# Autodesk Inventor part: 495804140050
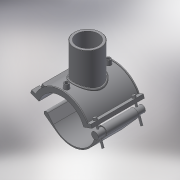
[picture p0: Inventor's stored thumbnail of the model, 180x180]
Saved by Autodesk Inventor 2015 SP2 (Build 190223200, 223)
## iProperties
Created: 2017-07
Part Number: 495804140050
Material: Generic
Description: PLASSON BRANCH SADDLE 140-50
Document SubType Name: Modeling
Designer: KIM
Density: 1 g/cm^3
Appearance: Default
Author: KIM
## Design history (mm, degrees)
derived "495804.ipt"
feature "Solid1::495804.ipt"
feature "Solid2::495804.ipt"
tag "TaggingFeature1"
body "Solid1"
body "Solid2"
other parameters: "d3" = 35, "d4" = 118, "d5" = 0, "d6" = 0.1, "d8" = 0, "d19" = 6, "d20" = 6, "d21" = 70.8, "d23" = 0, "d24" = 35.4, "d26" = 0, "d27" = 3, "d28" = 3, "d29" = 3, "d30" = 46.66667, "d31" = 6, "d32" = 0, "d33" = 0, "d34" = 0.6, "d40" = 84.24, "d41" = 55, "d43" = 0, "d45" = 0, "d47" = 174, "d50" = 0, "d70" = 15, "d72" = 0, "d73" = 6, "d75" = 5, "d76" = 0, "d77" = 7, "d79" = 15, "d80" = 47.2, "d82" = 5 deg, "d84" = 4, "d85" = 14, "d86" = 0, "d87" = 3, "d88" = 0, "d89" = 1, "d90" = 1, "d91" = 94.4, "d92" = 0, "d93" = 0.5, "d94" = 73.68421, "d96" = 165.24, "d97" = 2.36, "d98" = 0, "d102" = 1.5, "d105" = 0, "d109" = -31, "d117" = 0.5, "d120" = 140 deg, "d121" = 24.228, "d122" = 20 deg, "d123" = 324, "d124" = 97.2, "d126" = 0, "d143" = 147, "d150" = 25.2, "d159" = 4.4, "d161" = 3.5, "d162" = 70.8, "d163" = 0, "d167" = 28, "d168" = 73.63636, "d173" = 1, "d176" = 20 deg, "d177" = 9.8, "d178" = 22, "d180" = 0, "d185" = 38.35, "d186" = 38.35, "d187" = 81, "d188" = 6.6, "d189" = 9.8, "d190" = 0, "d191" = 121.5, "d200" = 11, "d202" = 0, "d216" = 106.2, "d217" = 0, "d221" = 43.66, "d222" = 9.8, "d223" = 5.88, "d225" = 5.88, "d227" = 20.16, "d230" = 86.8, "d236" = 20 deg, "d237" = 88, "d238" = 20 deg, "d239" = 9.8, "H_" = 93, "L_" = 118, "d_t" = 6, "H_1" = 82, "d1" = 162, "d148" = 3.5, "d160" = 3.5
